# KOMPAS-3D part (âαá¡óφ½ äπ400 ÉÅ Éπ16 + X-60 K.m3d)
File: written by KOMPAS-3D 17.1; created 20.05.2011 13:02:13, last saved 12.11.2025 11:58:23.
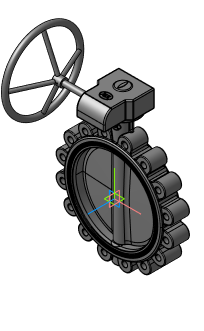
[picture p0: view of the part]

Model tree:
1. Плоскость XY
2. Плоскость ZX
3. Плоскость ZY
4. Ось X
5. Ось Y
6. Ось Z
7. Начало координат
8. Операция без истории:5

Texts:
  Viktor2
